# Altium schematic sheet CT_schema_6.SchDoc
size 218 x 258 mm
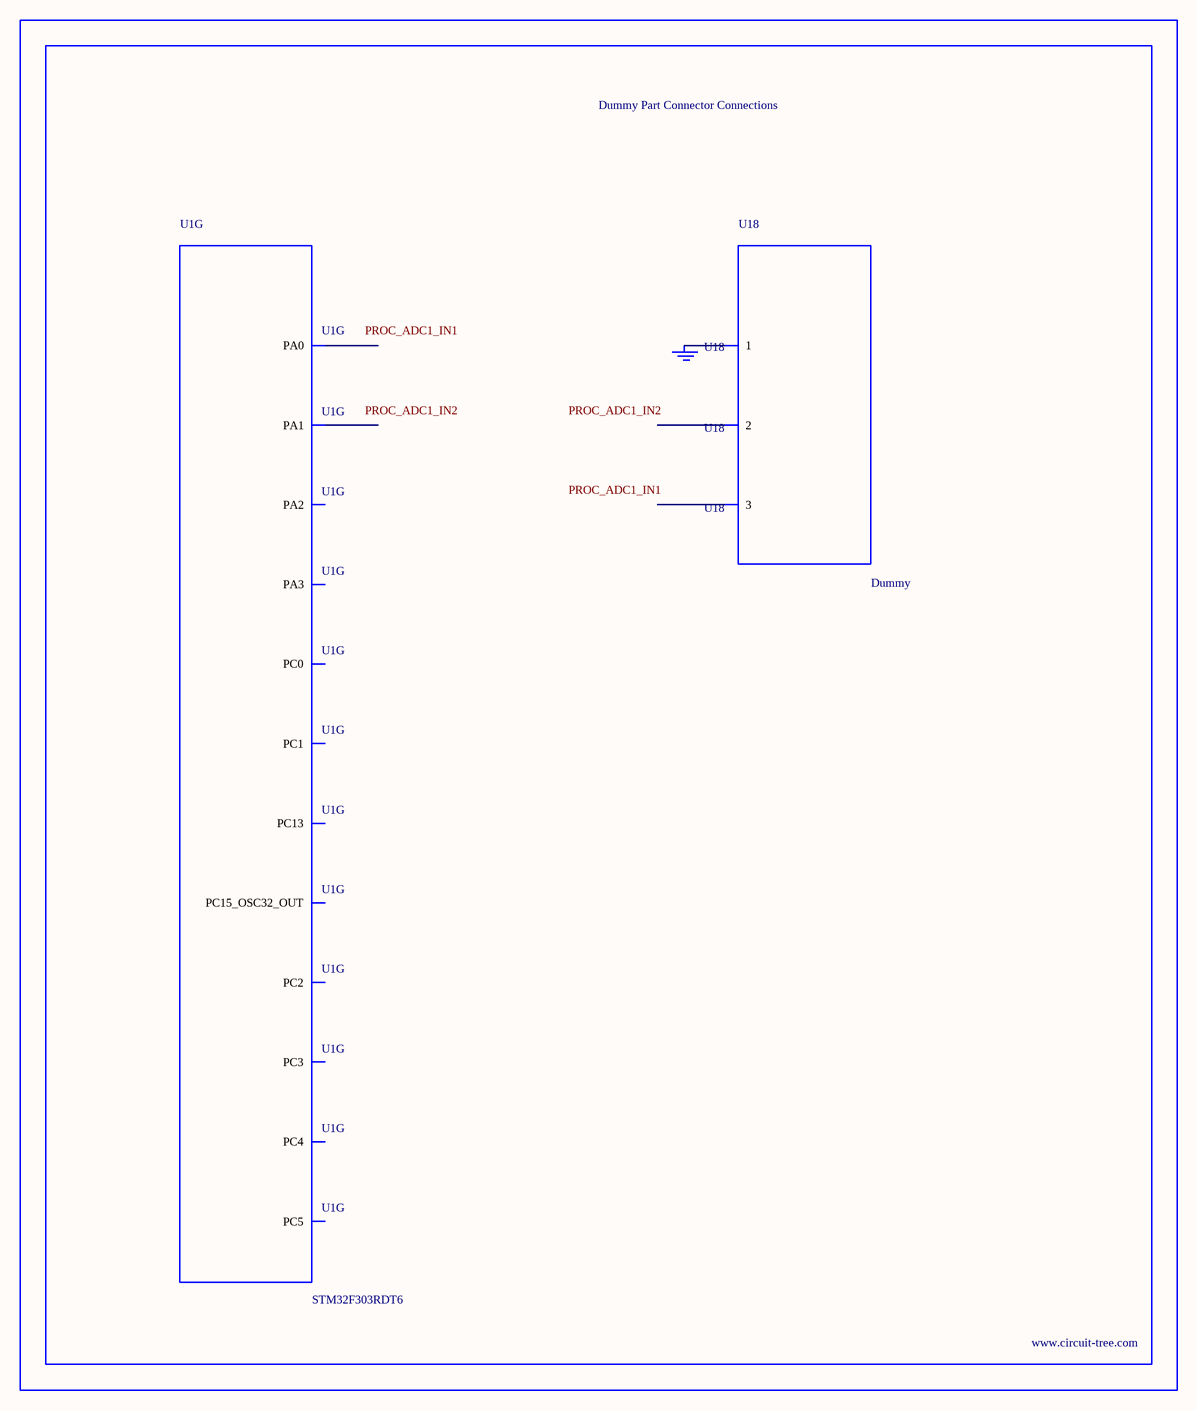
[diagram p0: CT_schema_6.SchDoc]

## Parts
BORDER5  (no value)
GND_INSTANCE_5_0  (no value)
U1  STM32F303RDT6  [LQFP64]  (part G of 7)
U18  Dummy  [DUMMY_PACKAGE_186]

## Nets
NetGND_INSTANCE_5_0_0: GND_INSTANCE_5_0.0(GND) U18.1

Not connected (* = marked no-connect by the designer): U1 2(PC13) 4(PC15_OSC32_OUT) 8(PC0) 9(PC1) 10(PC2) 11(PC3) 14(PA0) 15(PA1) 16(PA2) 17(PA3) 24(PC4) 25(PC5); U18 2 3

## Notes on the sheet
- Labels drawn without touching a wire or pin: PROC_ADC1_IN1, PROC_ADC1_IN2

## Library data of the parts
BORDER5 = BORDER_PAGE5
GND_INSTANCE_5_0 = GND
